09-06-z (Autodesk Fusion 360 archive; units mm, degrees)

design "09-06-z" references "09-KOTEI", "09-KADOU", "09-PIN"
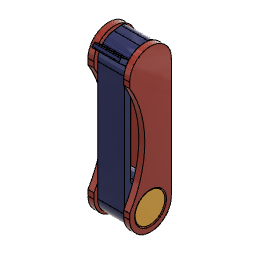
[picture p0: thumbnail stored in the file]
component_insert "コンポーネントの挿入1"
ground "固定"
component_insert "コンポーネントの挿入2"
joint "アセンブリ1" alignAngle 0 alignOffsetX 0 alignOffsetY 0 alignOffsetZ 0
component_insert "コンポーネントの挿入3"
joint "アセンブリ2" alignAngle 0 alignOffsetX 0 alignOffsetY 0 alignOffsetZ 0
component_insert "コンポーネントの挿入4"
joint "アセンブリ4" alignAngle 0 alignOffsetX 0 alignOffsetY 0 alignOffsetZ 0

design "09-KADOU"
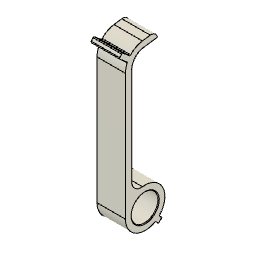
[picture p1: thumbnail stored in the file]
sketch "スケッチ1" plane through (0, 0, 0) normal (1, 0, 0) x axis (0, 0, -1)
  circle C1 centre (0, 0) radius 6.25
  point P1 (0, 0)
  point P2 (0, 0)
  coincident P1 P2
  dimension "d1" diameter C1 = 12.5
extrude "押し出し1" new body sketch "スケッチ1" distance 9
sketch "スケッチ2" plane through (0, 0, 0) normal (1, 0, 0) x axis (0, 0, -1)
  line L1 (-4.25, 0) -> (-4.25, 40)
  line L2 (-6.25, 0) -> (-4.25, 0)
  line L3 (-6.25, 40) -> (-6.25, 0)
  line L4 (3.8647, 44.8349) -> (-0.5915, 44.2086)
  line L5 (3.5864, 46.8155) -> (3.8647, 44.8349)
  line L6 (-0.8698, 46.1892) -> (3.5864, 46.8155)
  circle C1 centre (0, 0) radius 6.25
  arc A1 centre (0, 40) radius 4.25 clockwise from (-4.25, 40) to (-0.5915, 44.2086)
  arc A2 centre (0, 40) radius 6.25 clockwise from (-6.25, 40) to (-0.8698, 46.1892)
  point P1 (0, 0)
  point P8 (0, 40)
  point P12 (0, 40)
  vertical L1
  horizontal L2
  vertical L3
  coincident P1 L2
  tangent L3 C1
  perpendicular L4 L5
  perpendicular L5 L6
  coincident P8 P12
  vertical P1 P8
  tangent L1 A1
  tangent A1 L4
  tangent L3 A2
  dimension "d5" distance L1 L3 = 2
  dimension "d18" distance L4 L6 = 2
  dimension "d21" distance P8 L5 = 4.5
  dimension "d22" angle L1 L4 = 98
  dimension "d54" distance P1 P12 = 40
extrude "押し出し2" add sketch "スケッチ2" profile of L1 L3 C1 distance 9
sketch "スケッチ4" plane through (0, 0, 0) normal (1, 0, 0) x axis (0, 0, -1)
  line L1 (5.3033, -5.3033) -> (0, 0)
  line L2 (4.2426, -6.364) -> (5.3033, -5.3033)
  line L3 (-1.0607, -1.0607) -> (4.2426, -6.364)
  line L4 (0, 0) -> (-1.0607, -1.0607)
  line L5 (-22.5, 0) -> (-1.75, 0)
  point P1 (0, 0)
  point P2 (0, 0)
  perpendicular L1 L2
  parallel L1 L3
  parallel L2 L4
  coincident P1 P2
  dimension "d24" angle L1 L5 = 45
  dimension "d25" distance L2 L4 = 7.5
  dimension "d26" distance L1 L3 = 1.5
extrude "押し出し4" add sketch "スケッチ4" profile of L1 L2 L3 L4 distance 9
joint_origin "JointOrigin1" OffsetX 0 OffsetY 0 OffsetZ 0 AngleZ 0
sketch "スケッチ5" plane through (0, 0, 0) normal (1, 0, 0) x axis (0, 0, -1)
  line L1 (0, 40) -> (-7.2774, 46.1065)
  line L2 (-0.9642, 38.8509) -> (0, 40)
  line L3 (-8.2416, 44.9574) -> (-0.9642, 38.8509)
  line L4 (-7.2774, 46.1065) -> (-8.2416, 44.9574)
  line L5 (0, 22.5) -> (0, 1.75)
  arc A1 centre (0, 40) radius 4.25 clockwise from (-4.25, 40) to (-0.5915, 44.2086)
  point P3 (0, 40)
  point P8 (0, 40)
  perpendicular L1 L2
  parallel L1 L3
  parallel L2 L4
  coincident P3 P8
  dimension "d33" angle L1 L5 = 50
  dimension "d34" distance L1 L3 = 1.5
  dimension "d35" distance L2 L4 = 9.5
extrude "押し出し5" add sketch "スケッチ5" profile of L1 L3 L4 A1 distance 9
fillet "フィレット3" radius 2
sketch "スケッチ6" plane through (0, 43.4339, 6.1042) normal (0, -0.9903, -0.1392) x axis (-1, 0, 0)
  line L1 (-4.5, 10.0669) -> (4.5, 10.0669)
  line L2 (-4.5, 5.5669) -> (-4.5, 10.0669)
  line L3 (4.5, 5.5669) -> (-4.5, 5.5669)
  line L4 (4.5, 10.0669) -> (4.5, 5.5669)
  circle C1 centre (0, 8.0669) radius 0.75
  point P1 (0, 0)
  point P6 (0, 8.0669)
  vertical P1 P6
  dimension "d40" distance L1 P6 = 2
  dimension "d41" diameter C1 = 1.5
extrude "押し出し6" add sketch "スケッチ6" profile of C1 along normal blind 0.7
fillet "フィレット4" radius 0.6
fillet "フィレット5" radius 3
fillet "フィレット6" radius 0.3
hole "穴" HoleDepth 9 HoleDiameter 8.5 TipAngle 118
chamfer "面取り" distance 0.2

design "09-KOTEI"
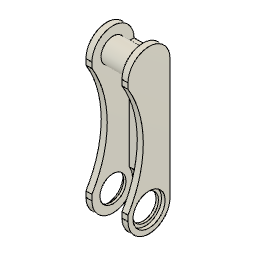
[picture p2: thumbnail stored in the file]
sketch "スケッチ1" plane through (0, 0, 0) normal (1, 0, 0) x axis (0, 0, -1)
  circle C1 centre (0, 40) radius 4
  point P1 (0, 0)
  point P2 (0, 40)
  vertical P1 P2
  dimension "d1" diameter C1 = 8
  dimension "d29" distance P1 P2 = 40
extrude "押し出し1" new body sketch "スケッチ1" + "スケッチ5" profile of S1:C1 distance 10
sketch "スケッチ2" plane through (5, 0, 0) normal (1, 0, 0) x axis (0, 0, -1)
  line L1 (-7, 0) -> (-7, 40)
  line L2 (7, 40) -> (7, 0)
  line L3 (0, 0) -> (0, 40)
  circle C1 centre (0, 40) radius 4
  arc A1 centre (0, 0) radius 7 clockwise from (7, 0) to (-7, 0)
  arc A2 centre (0, 40) radius 7 clockwise from (-7, 40) to (7, 40)
  point P7 (0, 40)
  point P9 (0, 40)
  point P8 (0, 0)
  tangent L1 A1
  tangent A1 L2
  parallel L1 L2
  tangent L2 A2
  tangent L1 A2
  vertical L3
  coincident P7 P9
  concentric C1 A2
  dimension "d4" radius A2 = 7
  dimension "d5" distance P7 P8 = 40
extrude "押し出し2" add sketch "スケッチ2" profile of C1 L1 A1 L2 A2 along normal blind 2
mirror "ミラー" sketch "スケッチ5" mirrorStitchTolerance 0.1
sketch "スケッチ3" plane through (0, 0, 0) normal (1, 0, 0) x axis (0, 0, -1)
  line L1 (7, 40) -> (5.4, 40)
  line L2 (7, 0) -> (7, 40)
  line L3 (5.4, 0) -> (7, 0)
  line L4 (5.4, 40) -> (5.4, 0)
  point P3 (7, 40)
  point P6 (7, 40)
  point P4 (7, 0)
  point P7 (7, 0)
  horizontal L1
  vertical L2
  horizontal L3
  vertical L4
  coincident P3 P6
  coincident P4 P7
  dimension "d10" distance L2 L4 = 1.6
extrude "押し出し3" add sketch "スケッチ3" distance 10
sketch "スケッチ4" plane through (0, 0, 0) normal (1, 0, 0) x axis (0, 0, -1)
  circle C1 centre (-36.9324, 20) radius 35
  arc A1 centre (0, 40) radius 7 clockwise from (-7, 40) to (7, 40)
  arc A2 centre (0, 0) radius 7 clockwise from (7, 0) to (-7, 0)
  tangent C1 A1
  tangent C1 A2
  dimension "d13" diameter C1 = 70
extrude "押し出し4" cut sketch "スケッチ4" profile of C1 no distance stored
sketch "スケッチ5" plane through (0, 0, 0) normal (1, 0, 0) x axis (0, 0, -1)
  circle C1 centre (0, 0) radius 6.5
  arc A1 centre (0, 0) radius 7 clockwise from (7, 0) to (-7, 0)
  concentric C1 A1
  dimension "d15" diameter C1 = 13
extrude "押し出し5" cut sketch "スケッチ5" profile of C1 distance 10
chamfer "面取り" distance 0.2
hole "穴1" HoleDepth 2 HoleDiameter 8.7 TipAngle 118 CBDepth 1.2 CBDiameter 10.7
hole "穴2" HoleDepth 2 HoleDiameter 8.7 TipAngle 118 CBDepth 1.2 CBDiameter 10.7
joint_origin "JointOrigin1" sketch "スケッチ5" OffsetX 0 OffsetY 0 OffsetZ 0 AngleZ 0

design "09-PIN"
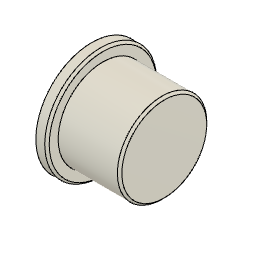
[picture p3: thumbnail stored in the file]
sketch "スケッチ" plane through (0, 0, 0) normal (0, 0, 1) x axis (1, 0, 0)
  line L1 (0, 5) -> (0, 0)
  line L2 (1, 5) -> (0, 5)
  line L3 (1, 4) -> (1, 5)
  line L4 (6.5, 4) -> (1, 4)
  line L5 (6.5, 0) -> (6.5, 4)
  line L6 (0, 0) -> (6.5, 0)
  point P1 (0, 0)
  point P2 (0, 0)
  point P8 (0, 0)
  point P3 (0, 5)
  point P4 (1, 5)
  point P5 (1, 4)
  point P6 (6.5, 4)
  coincident P1 P2
  vertical L1
  perpendicular L1 L2
  perpendicular L2 L3
  perpendicular L3 L4
  perpendicular L4 L5
  coincident P1 P8
  horizontal L6
  dimension "d1" = 8
  dimension "d2" = 10
  dimension "d3" distance P3 P4 = 1
  dimension "d4" distance P5 P6 = 5.5
revolve "回転" sketch "スケッチ" AlongAngle 360
chamfer "面取り" distance 0.2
